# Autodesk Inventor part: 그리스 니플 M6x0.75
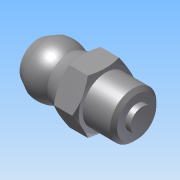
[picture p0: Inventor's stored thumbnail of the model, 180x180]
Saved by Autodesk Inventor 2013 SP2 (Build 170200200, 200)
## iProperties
Created: 2025-10
Part Number: 그리스 니플 M6x0.75
Material: Generic
Document SubType Name: Modeling
Designer: 601
Density: 1 g/cm^3
Author: 601
변환 표준: STEP AP214IS
전처리기: Build: 200, Release: 2013 SP2 Update 6 - Date: Thu 07/17/2014
전송 단위: 밀리미터
불확실성: 0.01
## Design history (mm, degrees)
node "그리스 니플 M6x0.751"
body "Solid1"
node "기준1"
